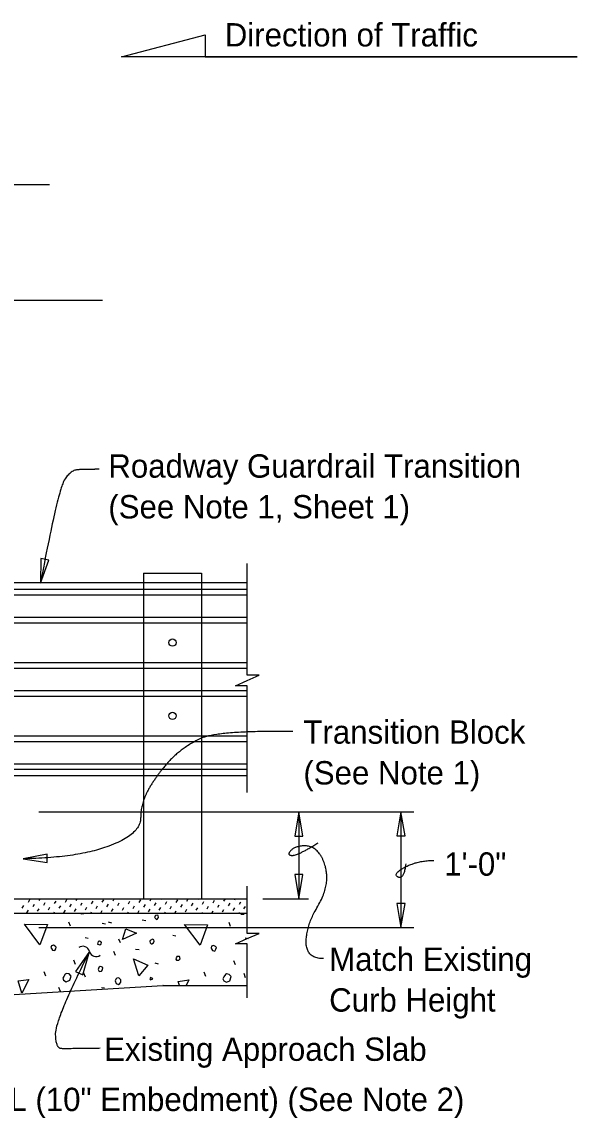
# Model space of a CAD drawing. Extents: x 21526.6 to 21595.9, y 56117 to 56157.3.
# Drawn here: x 21539.73 to 21544.53, y 56132.57 to 56142.03 of the extents above; entities that cross this region are included whole.
import ezdxf

# ---------------------------------------------------------------- set-up
doc = ezdxf.new("R2010")
doc.units = 0
for name, color, linetype in [('AdhocPoint_dp', 7, 'Continuous'), ('Border', 7, 'Continuous'), ('Patterning', 7, 'Continuous'), ('PlotBorder_dp', 7, 'Continuous'), ('SheetBorder_dp', 7, 'Continuous')]:
    doc.layers.add(name, color=color, linetype=linetype)

msp = doc.modelspace()

# ---------------------------------------------------------------- linework, layer by layer
at = {"layer": 'AdhocPoint_dp'}
for p, q in [((21535.7321, 56134.4601), (21541.6829, 56134.4601)), ((21537.582, 56134.335), (21541.6829, 56134.335)), ((21536.7321, 56133.4601), (21540.9521, 56133.71)), ((21540.9521, 56133.7101), (21541.6829, 56133.7101))]:
    msp.add_line(p, q, dxfattribs=at)
at = {"layer": 'Patterning'}
for p, q in [((21540.7867, 56137.2725), (21540.7867, 56134.4601)), ((21540.7867, 56137.2725), (21541.2867, 56137.2725)), ((21541.2867, 56137.2725), (21541.2867, 56134.4601)), ((21534.1592, 56137.1336), (21541.6829, 56137.1336)), ((21534.1592, 56137.0854), (21541.6829, 56137.0854)), ((21534.1592, 56136.8926), (21541.6829, 56136.8926)), ((21534.1592, 56136.8444), (21541.6829, 56136.8444)), ((21534.1592, 56136.5004), (21541.6829, 56136.5004)), ((21534.1592, 56136.4522), (21541.6829, 56136.4522)), ((21534.1592, 56136.2594), (21541.6829, 56136.2594)), ((21534.1592, 56136.2112), (21541.6829, 56136.2112)), ((21534.1592, 56135.8673), (21541.6829, 56135.8673)), ((21534.1592, 56135.8191), (21541.6829, 56135.8191)), ((21534.1592, 56135.6262), (21541.6829, 56135.6262)), ((21534.1592, 56135.578), (21541.6829, 56135.578)), ((21539.7909, 56134.4317), (21539.8039, 56134.4541)), ((21539.884, 56134.4447), (21539.8929, 56134.46)), ((21539.9771, 56134.4577), (21539.9785, 56134.46)), ((21540.0172, 56134.4176), (21540.0301, 56134.44)), ((21540.1103, 56134.4306), (21540.1232, 56134.4529)), ((21540.2034, 56134.4435), (21540.2129, 56134.46)), ((21540.2965, 56134.4565), (21540.2985, 56134.46)), ((21540.3366, 56134.4164), (21540.3495, 56134.4388)), ((21540.4297, 56134.4294), (21540.4426, 56134.4518)), ((21540.5228, 56134.4423), (21540.533, 56134.46)), ((21540.6159, 56134.4553), (21540.6186, 56134.46)), ((21540.6559, 56134.4152), (21540.6689, 56134.4376)), ((21540.749, 56134.4282), (21540.762, 56134.4506)), ((21540.8421, 56134.4412), (21540.8531, 56134.46)), ((21540.9352, 56134.4541), (21540.9387, 56134.46)), ((21540.9753, 56134.4141), (21540.9883, 56134.4364)), ((21541.0684, 56134.427), (21541.0814, 56134.4494)), ((21541.1615, 56134.44), (21541.1731, 56134.46)), ((21541.2546, 56134.4529), (21541.2587, 56134.46)), ((21541.2947, 56134.4129), (21541.3077, 56134.4353)), ((21541.3878, 56134.4258), (21541.4008, 56134.4482)), ((21541.4809, 56134.4388), (21541.4932, 56134.46)), ((21541.574, 56134.4518), (21541.5788, 56134.46)), ((21541.6141, 56134.4117), (21541.627, 56134.4341)), ((21539.7379, 56134.3787), (21539.7508, 56134.4011)), ((21539.7779, 56134.3386), (21539.7909, 56134.361)), ((21539.831, 56134.3917), (21539.8439, 56134.4141)), ((21539.871, 56134.3516), (21539.884, 56134.374)), ((21539.9241, 56134.4046), (21539.937, 56134.427)), ((21539.9641, 56134.3646), (21539.9771, 56134.387)), ((21540.0103, 56134.335), (21540.0172, 56134.3469)), ((21540.0572, 56134.3775), (21540.0702, 56134.3999)), ((21540.0973, 56134.3375), (21540.1103, 56134.3598)), ((21540.1504, 56134.3905), (21540.1633, 56134.4129)), ((21540.1904, 56134.3504), (21540.2034, 56134.3728)), ((21540.2435, 56134.4034), (21540.2564, 56134.4258)), ((21540.2835, 56134.3634), (21540.2965, 56134.3858)), ((21540.3304, 56134.335), (21540.3366, 56134.3457)), ((21540.3766, 56134.3763), (21540.3896, 56134.3987)), ((21540.4167, 56134.3363), (21540.4297, 56134.3587)), ((21540.4697, 56134.3893), (21540.4827, 56134.4117)), ((21540.5098, 56134.3492), (21540.5228, 56134.3716)), ((21540.5628, 56134.4023), (21540.5758, 56134.4247)), ((21540.6029, 56134.3622), (21540.6159, 56134.3846)), ((21540.6504, 56134.335), (21540.6559, 56134.3445)), ((21540.696, 56134.3752), (21540.709, 56134.3976)), ((21540.7361, 56134.3351), (21540.749, 56134.3575)), ((21540.7891, 56134.3881), (21540.8021, 56134.4105)), ((21540.8292, 56134.3481), (21540.8421, 56134.3705)), ((21540.8822, 56134.4011), (21540.8952, 56134.4235)), ((21540.9223, 56134.361), (21540.9352, 56134.3834)), ((21540.9705, 56134.335), (21540.9753, 56134.3433)), ((21541.0154, 56134.374), (21541.0283, 56134.3964)), ((21541.0561, 56134.335), (21541.0684, 56134.3563)), ((21541.1085, 56134.387), (21541.1214, 56134.4093)), ((21541.1486, 56134.3469), (21541.1615, 56134.3693)), ((21541.2016, 56134.3999), (21541.2145, 56134.4223)), ((21541.2417, 56134.3598), (21541.2546, 56134.3822)), ((21541.2905, 56134.335), (21541.2947, 56134.3422)), ((21541.3348, 56134.3728), (21541.3477, 56134.3952)), ((21541.3761, 56134.335), (21541.3878, 56134.3551)), ((21541.4279, 56134.3858), (21541.4408, 56134.4082)), ((21541.4679, 56134.3457), (21541.4809, 56134.3681)), ((21541.521, 56134.3987), (21541.5339, 56134.4211)), ((21541.561, 56134.3587), (21541.574, 56134.3811)), ((21541.6106, 56134.335), (21541.6141, 56134.341)), ((21541.6541, 56134.3716), (21541.6671, 56134.394)), ((21540.1542, 56134.2237), (21540.1418, 56134.2573)), ((21540.4282, 56134.2502), (21540.4565, 56134.2431)), ((21540.4799, 56134.2595), (21540.5082, 56134.2524)), ((21540.7756, 56134.2785), (21540.8056, 56134.2732)), ((21541.5375, 56134.2202), (21541.5251, 56134.2537)), ((21541.0389, 56134.1459), (21541.0655, 56134.1406)), ((21540.2815, 56134.1247), (21540.308, 56134.1194)), ((21540.586, 56134.0783), (21540.5736, 56134.1119)), ((21541.6647, 56134.1212), (21541.6913, 56134.1159)), ((21540.5435, 56133.9687), (21540.5294, 56134.004)), ((21540.7154, 56134.0239), (21540.7473, 56134.0204)), ((21540.1984, 56133.8931), (21540.1842, 56133.9285)), ((21540.8834, 56133.9055), (21540.9117, 56133.8984)), ((21541.5817, 56133.8896), (21541.5675, 56133.9249)), ((21539.9421, 56133.7924), (21539.9279, 56133.8277)), ((21540.2854, 56133.7813), (21540.2713, 56133.8167)), ((21541.3253, 56133.7888), (21541.3112, 56133.8242)), ((21541.6687, 56133.7778), (21541.6546, 56133.8131)), ((21540.0676, 56133.6598), (21540.0552, 56133.6934)), ((21540.4233, 56133.6929), (21540.4481, 56133.6894))]:
    msp.add_line(p, q, dxfattribs=at)
for points in [[(21540.2429, 56134.335), (21540.2461, 56134.3298), (21540.2691, 56134.3315), (21540.2725, 56134.335)], [(21541.624, 56134.335), (21541.6294, 56134.3262), (21541.6524, 56134.328), (21541.6594, 56134.335)], [(21540.8869, 56134.2909), (21540.8975, 56134.2803), (21540.9081, 56134.2873), (21540.9152, 56134.2979), (21540.9117, 56134.3156), (21540.9028, 56134.3174), (21540.8905, 56134.3156), (21540.8799, 56134.305), (21540.8869, 56134.2909)], [(21539.8908, 56134.0628), (21539.7564, 56134.2396), (21539.9562, 56134.2378), (21539.8908, 56134.0628)], [(21540.6041, 56134.107), (21540.6324, 56134.1989), (21540.7261, 56134.1618), (21540.6041, 56134.107)], [(21541.2741, 56134.0593), (21541.1397, 56134.2361), (21541.3395, 56134.2343), (21541.2741, 56134.0593)], [(21539.9898, 56134.031), (21539.9986, 56134.0151), (21540.0198, 56134.0116), (21540.0287, 56134.0275), (21540.0322, 56134.0416), (21540.0234, 56134.0505), (21540.0075, 56134.0593), (21539.9915, 56134.054), (21539.9862, 56134.0381), (21539.9898, 56134.031)], [(21540.3893, 56134.0664), (21540.4087, 56134.0611), (21540.4211, 56134.0699), (21540.4229, 56134.0823), (21540.4193, 56134.0858), (21540.4052, 56134.0929), (21540.3928, 56134.0911), (21540.3911, 56134.0787), (21540.3893, 56134.0664)], [(21540.8516, 56134.0717), (21540.8586, 56134.0717), (21540.8728, 56134.0787), (21540.8781, 56134.0946), (21540.8763, 56134.1035), (21540.8622, 56134.1106), (21540.8445, 56134.0999), (21540.841, 56134.0893), (21540.8445, 56134.0787), (21540.8516, 56134.0717)], [(21541.3731, 56134.0275), (21541.3819, 56134.0116), (21541.4031, 56134.008), (21541.4119, 56134.0239), (21541.4155, 56134.0381), (21541.4066, 56134.0469), (21541.3907, 56134.0558), (21541.3748, 56134.0505), (21541.3695, 56134.0345), (21541.3731, 56134.0275)], [(21541.0708, 56133.9302), (21541.092, 56133.9302), (21541.1026, 56133.9409), (21541.0973, 56133.9603), (21541.0743, 56133.9621), (21541.0708, 56133.9515), (21541.0655, 56133.9426), (21541.0708, 56133.9302), (21541.0672, 56133.9338)], [(21540.395, 56133.8485), (21540.4039, 56133.8326), (21540.4233, 56133.8343), (21540.4322, 56133.8467), (21540.4339, 56133.8662), (21540.4216, 56133.8715), (21540.4127, 56133.8732), (21540.4021, 56133.8697), (21540.3986, 56133.8662), (21540.395, 56133.8485)], [(21540.7468, 56133.7937), (21540.6991, 56133.9404), (21540.8246, 56133.8856), (21540.7468, 56133.7937)], [(21540.0958, 56133.7552), (21540.1188, 56133.7429), (21540.1489, 56133.7552), (21540.1613, 56133.7924), (21540.1436, 56133.81), (21540.1206, 56133.8153), (21540.11, 56133.8083), (21540.0976, 56133.7888), (21540.0888, 56133.7729), (21540.0958, 56133.7552)], [(21540.54, 56133.7495), (21540.5506, 56133.7283), (21540.5683, 56133.7177), (21540.5824, 56133.7283), (21540.5895, 56133.7389), (21540.5895, 56133.7601), (21540.5736, 56133.776), (21540.5541, 56133.7742), (21540.5453, 56133.7654), (21540.54, 56133.7495)], [(21540.8458, 56133.7583), (21540.8653, 56133.7672), (21540.8582, 56133.7742), (21540.8458, 56133.7795), (21540.8405, 56133.7672), (21540.8458, 56133.7583)], [(21541.4791, 56133.7517), (21541.5021, 56133.7393), (21541.5322, 56133.7517), (21541.5445, 56133.7888), (21541.5269, 56133.8065), (21541.5039, 56133.8118), (21541.4933, 56133.8047), (21541.4809, 56133.7853), (21541.4721, 56133.7694), (21541.4791, 56133.7517)], [(21539.7352, 56133.6456), (21539.7016, 56133.7499), (21539.7953, 56133.7623), (21539.7352, 56133.6456)], [(21540.9547, 56133.71), (21540.9537, 56133.7106), (21540.9522, 56133.71)], [(21541.0966, 56133.71), (21541.0849, 56133.7464), (21541.1786, 56133.7588), (21541.1535, 56133.71)]]:
    msp.add_lwpolyline(points, dxfattribs=at)
at = {"layer": 'PlotBorder_dp'}
for p, q in [((21540.5963, 56141.7314), (21541.318, 56141.923)), ((21541.318, 56141.923), (21541.3196, 56141.7314)), ((21544.4067, 56141.7314), (21540.5963, 56141.7314)), ((21541.3196, 56141.7314), (21544.533, 56141.7314)), ((21544.533, 56141.7314), (21544.4067, 56141.7314)), ((21539.9741, 56140.6266), (21528.4455, 56140.6266)), ((21540.4322, 56139.6267), (21535.1627, 56139.6267)), ((21539.8821, 56135.2101), (21543.1218, 56135.2101)), ((21542.129, 56135.2101), (21542.129, 56134.4601)), ((21543.0111, 56135.2102), (21543.0111, 56134.2102)), ((21541.8169, 56134.4601), (21542.2116, 56134.4601)), ((21539.8821, 56134.2101), (21543.1218, 56134.2101))]:
    msp.add_line(p, q, dxfattribs=at)
for points in [[(21539.8946, 56137.1866), (21539.9683, 56137.3845), (21539.899, 56137.3977)], [(21542.129, 56135.2101), (21542.0937, 56135.0018), (21542.1642, 56135.0018)], [(21543.0111, 56135.2102), (21542.9758, 56135.0019), (21543.0464, 56135.0019)], [(21539.7444, 56134.8051), (21539.9532, 56134.7733), (21539.9521, 56134.8439)], [(21542.129, 56134.4601), (21542.1642, 56134.6683), (21542.0937, 56134.6683)], [(21543.0111, 56134.2102), (21543.0464, 56134.4184), (21542.9758, 56134.4184)], [(21540.3202, 56134.0044), (21540.1971, 56133.8327), (21540.2605, 56133.8018)]]:
    msp.add_lwpolyline(points, close=True, dxfattribs=at)
for points in [[(21541.6829, 56135.3777), (21541.6829, 56136.3003), (21541.5795, 56136.3003), (21541.6829, 56136.3453), (21541.7862, 56136.3903), (21541.6829, 56136.3903), (21541.6829, 56137.3551)], [(21541.6829, 56133.6036), (21541.6829, 56134.0708), (21541.5795, 56134.0708), (21541.6829, 56134.1158), (21541.7862, 56134.1608), (21541.6829, 56134.1608), (21541.6829, 56134.5682)]]:
    msp.add_lwpolyline(points, dxfattribs=at)
for centre, start, end in [((21540.2618, 56133.9896), 14.54134, 126.26856), ((21540.3772, 56134.0195), 194.54134, 306.26856)]:
    msp.add_arc(centre, 0.0596, start, end, dxfattribs=at)
for points in [[(21540.4034, 56138.1693), (21540.2833, 56138.1693), (21540.1525, 56138.1622), (21540.0465, 56137.9819), (21539.8946, 56137.1866)], [(21542.0754, 56135.9047), (21541.4139, 56135.9116), (21541.1398, 56135.7744), (21540.9568, 56135.6032), (21540.7613, 56135.3058), (21540.7613, 56135.0162), (21540.2137, 56134.8128), (21539.7444, 56134.8049)], [(21542.3427, 56133.9425), (21542.1919, 56133.9425), (21542.1919, 56134.2238), (21542.3701, 56134.5256), (21542.3701, 56134.7451), (21542.2673, 56134.9166), (21542.0959, 56134.9166), (21542.0206, 56134.8343), (21542.1234, 56134.8343), (21542.2947, 56134.944)], [(21543.0526, 56134.7626), (21543.0366, 56134.6212), (21542.9352, 56134.6732), (21543.1526, 56134.7906), (21543.2939, 56134.7906)], [(21540.4101, 56133.1678), (21540.1274, 56133.1634), (21540.0268, 56133.1666), (21540.0268, 56133.4222), (21540.3202, 56134.0043)]]:
    msp.add_open_spline(points, degree=2, dxfattribs=at)
at = {"layer": 'SheetBorder_dp'}
for p, q in [((21541.6829, 56137.1892), (21534.1592, 56137.1892)), ((21541.6829, 56135.5225), (21534.1592, 56135.5225))]:
    msp.add_line(p, q, dxfattribs=at)
for centre in [(21541.0367, 56136.6724), (21541.0367, 56136.0393)]:
    msp.add_circle(centre, 0.0312, dxfattribs=at)

# ---------------------------------------------------------------- texts
at = {"layer": 'Border'}
msp.add_text('Direction of Traffic', height=0.2016, rotation=359.99977, dxfattribs=at).set_placement((21541.4883, 56141.8217))
for s, p in [('1\'-0"', (21543.3847, 56134.659)), ('Existing Approach Slab', (21540.4455, 56133.0596)), ('Dowel Bars 4L (10" Embedment) (See Note 2)', (21538.0238, 56132.6259))]:
    msp.add_text(s, height=0.2016, dxfattribs=at).set_placement(p)
at = {"layer": 'PlotBorder_dp'}
for s, p in [('Roadway Guardrail Transition', (21540.4819, 56138.0972)), ('(See Note 1, Sheet 1)', (21540.4819, 56137.7452)), ('Transition Block', (21542.1678, 56135.799)), ('(See Note 1)', (21542.1678, 56135.447)), ('Match Existing ', (21542.3904, 56133.8368)), ('Curb Height', (21542.3904, 56133.4848))]:
    msp.add_text(s, height=0.2016, dxfattribs=at).set_placement(p)

doc.saveas('drawing.dxf')
